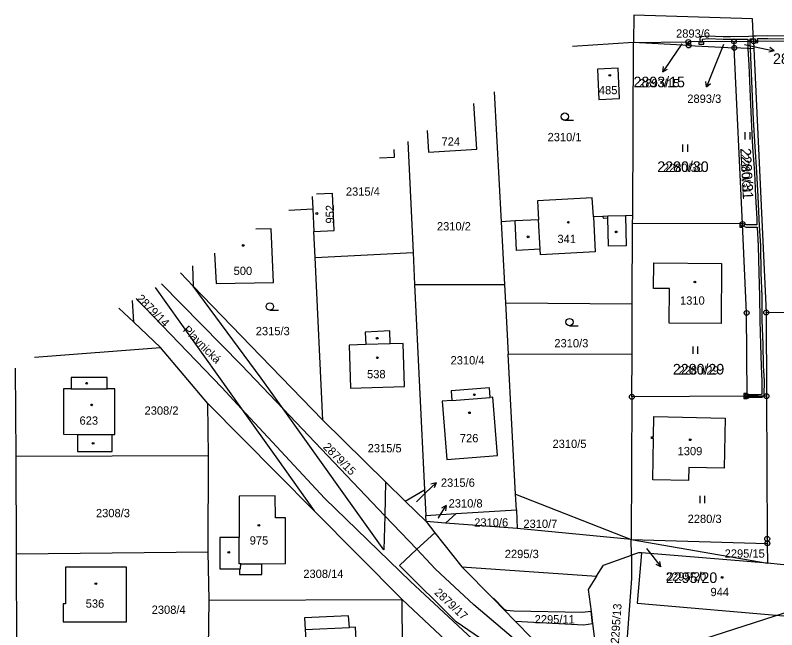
# Model space of a CAD drawing. Extents: x -758836 to -757729, y -1175316 to -1174366.
# Drawn here: x -758589.2 to -758433.4, y -1174763.3 to -1174637.5 of the extents above; entities that cross this region are included whole.
import ezdxf

# ---------------------------------------------------------------- set-up
doc = ezdxf.new("R2010")
doc.units = 0
for name, color, linetype in [('_NOR-pomocná', 7, 'Continuous'), ('Hranice parcel', 7, 'Continuous'), ('Parcelní čísla', 7, 'Continuous'), ('Pop  PČ popisy', 7, 'Continuous'), ('Vnitřní kresba', 7, 'Continuous'), ('Věcná břemena k části', 7, 'Continuous'), ('Značky bodu BP', 7, 'Continuous'), ('Značky budov', 7, 'Continuous'), ('Značky kultur', 7, 'Continuous')]:
    doc.layers.add(name, color=color, linetype=linetype)

msp = doc.modelspace()

# ---------------------------------------------------------------- linework, layer by layer
at = {"layer": '_NOR-pomocná'}
msp.add_lwpolyline([(-758517.54, -1174787.42), (-758417.59, -1174755.22), (-758372.07, -1174896.57), (-758472.01, -1174928.76)], close=True, dxfattribs=at)
at = {"layer": 'Hranice parcel'}
for p, q in [((-758462.68, -1174643.09), (-758475.19, -1174643.89)), ((-758462.85, -1174678.46), (-758462.68, -1174643.09)), ((-758462.68, -1174643.09), (-758451.46, -1174642.95)), ((-758451.39, -1174643.67), (-758462.68, -1174643.09)), ((-758442.12, -1174642.84), (-758451.46, -1174642.95)), ((-758451.46, -1174642.95), (-758451.39, -1174643.67)), ((-758442.12, -1174642.84), (-758438.13, -1174642.79)), ((-758442.06, -1174644.14), (-758442.12, -1174642.84)), ((-758438.13, -1174642.79), (-758413.7, -1174642.5)), ((-758438.13, -1174642.79), (-758438.05, -1174644.35)), ((-758451.39, -1174643.67), (-758442.06, -1174644.14)), ((-758438.05, -1174644.35), (-758442.06, -1174644.14)), ((-758440.39, -1174680.2), (-758442.06, -1174644.14)), ((-758438.05, -1174644.35), (-758435.54, -1174698.32)), ((-758491.19, -1174653.13), (-758489.78, -1174679.76)), ((-758508.89, -1174663.35), (-758507.79, -1174686.07)), ((-758528.42, -1174674.62), (-758528.3, -1174677.14)), ((-758533.22, -1174677.4), (-758528.3, -1174677.14)), ((-758528.3, -1174677.14), (-758528.09, -1174681.75)), ((-758462.86, -1174680.09), (-758462.85, -1174678.46)), ((-758489.78, -1174679.76), (-758489.1, -1174692.62)), ((-758462.93, -1174696.59), (-758462.86, -1174680.09)), ((-758440.39, -1174680.2), (-758462.86, -1174680.09)), ((-758527.85, -1174687.07), (-758528.09, -1174681.75)), ((-758527.85, -1174687.07), (-758507.79, -1174686.07)), ((-758526.24, -1174720.38), (-758527.85, -1174687.07)), ((-758507.79, -1174686.07), (-758507.47, -1174692.57)), ((-758555.41, -1174690.21), (-758552.78, -1174692.96)), ((-758552.91, -1174688.76), (-758552.78, -1174692.96)), ((-758507.47, -1174692.57), (-758489.1, -1174692.62)), ((-758507.47, -1174692.57), (-758505.43, -1174734.65)), ((-758489.1, -1174692.62), (-758488.9, -1174696.33)), ((-758488.9, -1174696.33), (-758488.35, -1174706.88)), ((-758488.9, -1174696.33), (-758462.93, -1174696.59)), ((-758462.98, -1174706.79), (-758462.93, -1174696.59)), ((-758414.62, -1174698.66), (-758435.54, -1174698.32)), ((-758435.54, -1174698.32), (-758435.46, -1174715.46)), ((-758559.48, -1174705.52), (-758564.95, -1174700.34)), ((-758585.29, -1174707.46), (-758559.48, -1174705.52)), ((-758549.77, -1174716.98), (-758559.48, -1174705.52)), ((-758488.35, -1174706.88), (-758462.98, -1174706.79)), ((-758486.83, -1174735.54), (-758488.35, -1174706.88)), ((-758463.02, -1174715.59), (-758462.98, -1174706.79)), ((-758589.2, -1174709.72), (-758589.11, -1174727.75)), ((-758463.02, -1174715.59), (-758463.16, -1174744.79)), ((-758439.46, -1174715.47), (-758463.02, -1174715.59)), ((-758435.46, -1174715.46), (-758439.46, -1174715.47)), ((-758549.68, -1174727.61), (-758549.77, -1174716.98)), ((-758526.24, -1174720.38), (-758513.43, -1174732.97)), ((-758589.11, -1174727.75), (-758549.68, -1174727.61)), ((-758549.7, -1174747.29), (-758549.68, -1174727.61)), ((-758589.11, -1174727.75), (-758589.01, -1174747.74)), ((-758513.43, -1174732.97), (-758509.4, -1174736.93)), ((-758509.4, -1174736.93), (-758505.43, -1174734.65)), ((-758505.43, -1174734.65), (-758505.18, -1174739.86)), ((-758509.4, -1174736.93), (-758505.12, -1174741.14)), ((-758486.66, -1174738.69), (-758486.83, -1174735.54)), ((-758486.83, -1174735.54), (-758463.16, -1174744.79)), ((-758510.04, -1174757.06), (-758528.03, -1174738.91)), ((-758505.18, -1174739.86), (-758498.99, -1174739.47)), ((-758505.12, -1174741.14), (-758505.18, -1174739.86)), ((-758498.99, -1174739.47), (-758501.16, -1174741.44)), ((-758498.99, -1174739.47), (-758486.66, -1174738.69)), ((-758486.66, -1174738.69), (-758486.46, -1174742.55)), ((-758501.16, -1174741.44), (-758505.12, -1174741.14)), ((-758505.12, -1174741.14), (-758503.32, -1174743.41)), ((-758486.46, -1174742.55), (-758501.16, -1174741.44)), ((-758463.16, -1174744.79), (-758486.46, -1174742.55)), ((-758503.32, -1174743.41), (-758497.78, -1174750.4)), ((-758463.16, -1174744.79), (-758435.31, -1174745.59)), ((-758463.12, -1174748.03), (-758463.16, -1174744.79)), ((-758463.16, -1174744.79), (-758435.29, -1174749.65)), ((-758435.31, -1174745.59), (-758435.29, -1174749.65)), ((-758589.01, -1174747.74), (-758549.7, -1174747.29)), ((-758589.01, -1174747.74), (-758588.92, -1174767.73)), ((-758549.49, -1174757.19), (-758549.7, -1174747.29)), ((-758435.29, -1174749.65), (-758461.07, -1174747.52)), ((-758497.78, -1174750.4), (-758470.24, -1174752.31)), ((-758429.95, -1174750.16), (-758435.29, -1174749.65)), ((-758549.63, -1174767.27), (-758549.49, -1174757.19)), ((-758549.49, -1174757.19), (-758510.04, -1174757.06)), ((-758509.88, -1174777.17), (-758510.04, -1174757.06)), ((-758501.06, -1174765.48), (-758510.04, -1174757.06)), ((-758471.37, -1174759.51), (-758471.06, -1174761.99))]:
    msp.add_line(p, q, dxfattribs=at)
for points in [[(-758438.13, -1174642.79), (-758438.34, -1174638.23), (-758462.65, -1174637.48), (-758462.68, -1174643.09)], [(-758469.78, -1174654.76), (-758465.54, -1174654.56), (-758465.83, -1174648.3), (-758470.08, -1174648.5), (-758469.78, -1174654.76)], [(-758504.93, -1174661.06), (-758504.66, -1174665.51), (-758494.75, -1174664.89), (-758495.34, -1174655.52)], [(-758514.67, -1174666.68), (-758511.56, -1174666.52), (-758511.64, -1174664.94)], [(-758528.09, -1174681.75), (-758523.95, -1174681.56), (-758524.31, -1174673.96), (-758527.53, -1174674.11)], [(-758462.85, -1174678.46), (-758464.35, -1174678.51), (-758467.93, -1174678.64), (-758468.93, -1174678.66), (-758470.9, -1174678.72), (-758471.11, -1174674.89), (-758482.35, -1174675.5), (-758482.15, -1174679.34), (-758486.93, -1174679.6), (-758489.78, -1174679.76)], [(-758439.46, -1174715.47), (-758439.54, -1174698.42), (-758440.39, -1174680.2)], [(-758548.41, -1174686.16), (-758548.11, -1174692.38), (-758536.32, -1174692.16), (-758536.83, -1174681.21), (-758539.96, -1174681.29)], [(-758458.58, -1174693.4), (-758458.55, -1174688.18), (-758444.67, -1174688.27), (-758444.76, -1174700.56), (-758455.38, -1174700.51), (-758455.33, -1174693.42), (-758458.58, -1174693.4)], [(-758560.57, -1174693.18), (-758542.88, -1174718.04), (-758535.53, -1174728.37), (-758528.03, -1174738.91)], [(-758552.78, -1174692.96), (-758539.03, -1174707.17), (-758526.24, -1174720.38)], [(-758513.43, -1174732.97), (-758513.55, -1174739.95), (-758513.8, -1174746.93), (-758534.39, -1174718.05), (-758538.89, -1174711.74), (-758552.78, -1174692.96)], [(-758564.95, -1174700.34), (-758565.19, -1174695.86)], [(-758564.95, -1174700.34), (-758567.98, -1174697.47)], [(-758512.53, -1174702.11), (-758517.56, -1174702.34), (-758517.48, -1174704.89), (-758520.88, -1174704.99), (-758520.61, -1174713.81), (-758509.54, -1174713.47), (-758509.81, -1174704.65), (-758512.45, -1174704.73), (-758512.53, -1174702.11)], [(-758579.33, -1174723.26), (-758576.48, -1174723.28), (-758576.48, -1174726.78), (-758569.38, -1174726.78), (-758569.38, -1174723.28), (-758568.82, -1174723.27), (-758568.82, -1174713.94), (-758570.37, -1174713.94), (-758570.37, -1174711.62), (-758577.77, -1174711.65), (-758577.77, -1174713.95), (-758579.33, -1174713.95), (-758579.33, -1174723.26)], [(-758499.86, -1174716.33), (-758501.81, -1174716.48), (-758500.88, -1174728.4), (-758490.54, -1174727.6), (-758491.47, -1174715.66), (-758492.01, -1174715.7), (-758492.16, -1174713.75), (-758500.01, -1174714.36), (-758499.86, -1174716.33)], [(-758435.46, -1174715.46), (-758435.32, -1174744.65), (-758435.31, -1174745.59)], [(-758528.03, -1174738.91), (-758535.61, -1174731.27), (-758549.77, -1174716.98)], [(-758458.53, -1174719.65), (-758443.93, -1174719.93), (-758444.11, -1174730.17), (-758451.37, -1174730.05), (-758451.42, -1174732.69), (-758458.75, -1174732.55), (-758458.61, -1174724.15), (-758458.99, -1174724.14), (-758458.98, -1174723.76), (-758458.6, -1174723.77), (-758458.53, -1174719.65)], [(-758543.34, -1174751.98), (-758538.77, -1174751.93), (-758538.76, -1174749.76), (-758533.87, -1174749.74), (-758533.92, -1174740.33), (-758535.97, -1174740.34), (-758536.01, -1174735.85), (-758543.38, -1174735.9), (-758543.36, -1174744.4), (-758547.35, -1174744.41), (-758547.36, -1174750.79), (-758543.31, -1174750.78), (-758543.34, -1174751.98)], [(-758466.28, -1174780.52), (-758466.54, -1174782.53), (-758466.7, -1174783.79), (-758499, -1174761.63), (-758510.58, -1174750.09), (-758507.04, -1174746.79), (-758503.32, -1174743.41)], [(-758461.07, -1174747.52), (-758461.67, -1174747.53), (-758463.12, -1174748.03)], [(-758461.07, -1174747.52), (-758461.94, -1174757.82), (-758430.38, -1174760.57), (-758429.49, -1174750.29)], [(-758470.24, -1174752.31), (-758468.8, -1174750.02), (-758463.12, -1174748.03)], [(-758463.12, -1174748.03), (-758463.07, -1174752.81), (-758464.86, -1174776.68)], [(-758578.91, -1174757.94), (-758579.4, -1174757.94), (-758579.39, -1174761.63), (-758566.45, -1174761.62), (-758566.46, -1174750.43), (-758578.93, -1174750.46), (-758578.91, -1174757.94)], [(-758497.78, -1174750.4), (-758491.43, -1174756.87), (-758486.91, -1174761.48), (-758479.92, -1174768.61), (-758466.28, -1174780.52)], [(-758470.24, -1174752.31), (-758471.93, -1174755.02), (-758471.37, -1174759.51)], [(-758529.99, -1174760.86), (-758529.84, -1174763.25), (-758529.19, -1174773.23), (-758523.57, -1174772.91), (-758523.49, -1174774.21), (-758519.13, -1174774.01), (-758519.21, -1174772.67), (-758519.57, -1174766.55), (-758519.37, -1174766.54), (-758519.6, -1174762.74), (-758520.82, -1174762.81), (-758521.03, -1174760.42), (-758529.99, -1174760.86)], [(-758471.06, -1174761.99), (-758469.72, -1174772.68), (-758464.86, -1174776.68)]]:
    msp.add_lwpolyline(points, dxfattribs=at)
at = {"layer": 'Pop  PČ popisy'}
for p, q in [((-758452.82, -1174643.33), (-758455.01, -1174646.57)), ((-758444.3, -1174643.49), (-758446.65, -1174649.39)), ((-758439.95, -1174643.49), (-758436.82, -1174644.15)), ((-758436.82, -1174644.15), (-758433.89, -1174644.77)), ((-758433.89, -1174644.77), (-758434.97, -1174645.06)), ((-758433.89, -1174644.77), (-758434.76, -1174644.08)), ((-758455.01, -1174646.57), (-758456.69, -1174649.06)), ((-758456.69, -1174649.06), (-758456.54, -1174647.95)), ((-758456.69, -1174649.06), (-758455.71, -1174648.51)), ((-758446.65, -1174649.39), (-758447.77, -1174652.17)), ((-758447.77, -1174652.17), (-758447.86, -1174651.06)), ((-758447.77, -1174652.17), (-758446.94, -1174651.43)), ((-758505.25, -1174735.25), (-758503.09, -1174733.17)), ((-758503.09, -1174733.17), (-758504.16, -1174733.5)), ((-758503.09, -1174733.17), (-758503.46, -1174734.22)), ((-758507.11, -1174737.06), (-758505.25, -1174735.25)), ((-758502.61, -1174740.36), (-758501.02, -1174737.81)), ((-758501.02, -1174737.81), (-758501.98, -1174738.4)), ((-758501.02, -1174737.81), (-758501.13, -1174738.93)), ((-758502.66, -1174740.44), (-758502.61, -1174740.36)), ((-758460, -1174746.66), (-758458.92, -1174748.03)), ((-758458.92, -1174748.03), (-758457.07, -1174750.4)), ((-758457.07, -1174750.4), (-758457.29, -1174749.3)), ((-758457.07, -1174750.4), (-758458.08, -1174749.91))]:
    msp.add_line(p, q, dxfattribs=at)
at = {"layer": 'Vnitřní kresba'}
for p, q in [((-758470.9, -1174678.72), (-758470.5, -1174685.92)), ((-758468.93, -1174678.66), (-758468.92, -1174679.01)), ((-758468.92, -1174679.01), (-758467.92, -1174678.98)), ((-758467.92, -1174678.98), (-758467.93, -1174678.64)), ((-758467.78, -1174684.77), (-758467.92, -1174678.98)), ((-758464.35, -1174678.51), (-758464.2, -1174684.69)), ((-758486.6, -1174685.67), (-758486.93, -1174679.6)), ((-758481.78, -1174685.4), (-758482.15, -1174679.34)), ((-758481.78, -1174685.4), (-758486.6, -1174685.67)), ((-758481.72, -1174686.55), (-758481.78, -1174685.4)), ((-758464.2, -1174684.69), (-758467.78, -1174684.77)), ((-758470.5, -1174685.92), (-758481.72, -1174686.55)), ((-758559.3, -1174692.46), (-758542.88, -1174709.13)), ((-758546.95, -1174713.65), (-758564.47, -1174695.44)), ((-758512.45, -1174704.73), (-758517.48, -1174704.89)), ((-758542.88, -1174709.13), (-758534.39, -1174718.05)), ((-758577.77, -1174713.95), (-758570.37, -1174713.94)), ((-758542.88, -1174718.04), (-758546.95, -1174713.65)), ((-758499.86, -1174716.33), (-758492.01, -1174715.7)), ((-758525.88, -1174736.38), (-758542.88, -1174718.04)), ((-758534.39, -1174718.05), (-758513.55, -1174739.95)), ((-758576.48, -1174723.28), (-758569.38, -1174723.28)), ((-758508.3, -1174753.37), (-758525.88, -1174736.38)), ((-758513.55, -1174739.95), (-758507.04, -1174746.79)), ((-758543.35, -1174749.79), (-758543.36, -1174744.4)), ((-758507.04, -1174746.79), (-758503.17, -1174750.86)), ((-758543.06, -1174749.77), (-758543.35, -1174749.79)), ((-758543.31, -1174750.78), (-758543.09, -1174750.77)), ((-758543.09, -1174750.77), (-758543.06, -1174749.77)), ((-758543.06, -1174749.77), (-758538.76, -1174749.76)), ((-758495.35, -1174758.17), (-758503.17, -1174750.86)), ((-758490.52, -1174769.94), (-758508.3, -1174753.37)), ((-758472, -1174777.9), (-758495.35, -1174758.17)), ((-758529.84, -1174763.25), (-758520.82, -1174762.81))]:
    msp.add_line(p, q, dxfattribs=at)
at = {"layer": 'Věcná břemena k části'}
msp.add_lwpolyline([(-758430.05, -1174641.8), (-758435.18, -1174641.73), (-758437.57, -1174641.76), (-758438.18, -1174641.8), (-758439.09, -1174641.86), (-758442.87, -1174641.88), (-758444.36, -1174641.9), (-758447.46, -1174641.75), (-758449.02, -1174641.91), (-758449.1, -1174642.48), (-758449.05, -1174642.92), (-758448.55, -1174642.92), (-758448.58, -1174642.37), (-758447.44, -1174642.25), (-758444.36, -1174642.4), (-758442.87, -1174642.38), (-758439.32, -1174642.36), (-758439.31, -1174642.8), (-758438.81, -1174642.8), (-758438.82, -1174642.34), (-758438.15, -1174642.3), (-758437.79, -1174642.28), (-758437.76, -1174642.79), (-758437.26, -1174642.78), (-758437.29, -1174642.26), (-758435.18, -1174642.23), (-758430.05, -1174642.3)], dxfattribs=at)
for points in [[(-758449.29, -1174643.43), (-758448.29, -1174643.41), (-758448.3, -1174642.91), (-758448.55, -1174642.92), (-758449.05, -1174642.92), (-758449.3, -1174642.92)], [(-758438.81, -1174642.8), (-758439.31, -1174642.8), (-758439.3, -1174643.39), (-758439.26, -1174644.29), (-758439.11, -1174647.73), (-758438.9, -1174652.59), (-758438.62, -1174658.85), (-758438.32, -1174664.49), (-758437.93, -1174669.64), (-758437.69, -1174674.61), (-758437.48, -1174679.17), (-758437.42, -1174680.38), (-758439.53, -1174680.36), (-758440.4, -1174680.08), (-758440.37, -1174680.61), (-758439.61, -1174680.86), (-758437.39, -1174680.88), (-758437.15, -1174684.71), (-758437.04, -1174690.21), (-758436.87, -1174695.01), (-758436.83, -1174699.96), (-758436.67, -1174704.86), (-758436.56, -1174709.29), (-758436.41, -1174712.36), (-758436.43, -1174715.04), (-758436.55, -1174715.13), (-758437.17, -1174715.16), (-758438.92, -1174715.19), (-758439.46, -1174715.18), (-758439.46, -1174715.47), (-758436.16, -1174715.46), (-758435.93, -1174715.28), (-758435.91, -1174712.34), (-758436.06, -1174709.27), (-758436.17, -1174704.84), (-758436.33, -1174699.94), (-758436.37, -1174694.99), (-758436.54, -1174690.19), (-758436.65, -1174684.69), (-758436.91, -1174680.62), (-758436.98, -1174679.15), (-758437.19, -1174674.59), (-758437.43, -1174669.6), (-758437.82, -1174664.45), (-758438.12, -1174658.83), (-758438.4, -1174652.57), (-758438.61, -1174647.71), (-758438.76, -1174644.31), (-758438.8, -1174643.37)], [(-758437.26, -1174642.78), (-758437.76, -1174642.79), (-758437.73, -1174643.13), (-758437.23, -1174643.09)], [(-758440.37, -1174680.61), (-758440.39, -1174680.2), (-758440.94, -1174680.2), (-758440.91, -1174680.85), (-758440.36, -1174680.83)], [(-758440.08, -1174715.47), (-758439.46, -1174715.47), (-758439.46, -1174715.18), (-758439.58, -1174715.18), (-758439.58, -1174714.93), (-758440.08, -1174714.93)], [(-758436.16, -1174715.46), (-758439.46, -1174715.47), (-758440.08, -1174715.47), (-758440.08, -1174715.93), (-758439.58, -1174715.93), (-758439.58, -1174715.68), (-758438.92, -1174715.69), (-758437.15, -1174715.66), (-758436.37, -1174715.63)], [(-758473.17, -1174759.76), (-758487.15, -1174759.46), (-758488.65, -1174759.34), (-758489.11, -1174759.1), (-758491.34, -1174756.78), (-758491.43, -1174756.87), (-758486.91, -1174761.48), (-758472.83, -1174762.24), (-758471.06, -1174761.99), (-758471.37, -1174759.51)]]:
    msp.add_lwpolyline(points, close=True, dxfattribs=at)
at = {"layer": 'Značky bodu BP'}
for centre, radius in [((-758451.46, -1174642.95), 0.5), ((-758451.39, -1174643.67), 0.5), ((-758451.46, -1174642.95), 0.0303), ((-758442.12, -1174642.84), 0.5), ((-758442.12, -1174642.84), 0.0303), ((-758438.13, -1174642.79), 0.5), ((-758438.13, -1174642.79), 0.0303), ((-758451.39, -1174643.67), 0.0303), ((-758442.06, -1174644.14), 0.5), ((-758442.06, -1174644.14), 0.0303), ((-758440.39, -1174680.2), 0.5), ((-758440.39, -1174680.2), 0.0303), ((-758439.54, -1174698.42), 0.5), ((-758435.54, -1174698.32), 0.5), ((-758439.54, -1174698.42), 0.0303), ((-758435.54, -1174698.32), 0.0303), ((-758463.02, -1174715.59), 0.5), ((-758439.46, -1174715.47), 0.5), ((-758435.46, -1174715.46), 0.5), ((-758463.02, -1174715.59), 0.0303), ((-758439.46, -1174715.47), 0.0303), ((-758435.46, -1174715.46), 0.0303), ((-758435.32, -1174744.65), 0.5), ((-758435.32, -1174744.65), 0.0303), ((-758435.31, -1174745.59), 0.5), ((-758435.31, -1174745.59), 0.0303)]:
    msp.add_circle(centre, radius, dxfattribs=at)
at = {"layer": 'Značky budov'}
for centre in [(-758467.54, -1174649.78), (-758527.48, -1174678.07), (-758476.02, -1174679.87), (-758466.22, -1174681.84), (-758484.25, -1174682.84), (-758542.55, -1174684.61), (-758450.12, -1174692.09), (-758515.14, -1174703.59), (-758515.11, -1174707.6), (-758574.57, -1174712.81), (-758495.26, -1174715.17), (-758573.55, -1174717.24), (-758496.26, -1174718.85), (-758451.07, -1174724.38), (-758573.26, -1174725.1), (-758539.34, -1174741.89), (-758545.5, -1174747.43), (-758444.55, -1174752.56), (-758572.69, -1174753.83)]:
    msp.add_circle(centre, 0.175, dxfattribs=at)
at = {"layer": 'Značky kultur'}
for p, q in [((-758476.74, -1174658.99), (-758474.99, -1174658.99)), ((-758439.84, -1174662.9), (-758439.84, -1174661.4)), ((-758438.84, -1174662.9), (-758438.84, -1174661.4)), ((-758452.57, -1174665.43), (-758452.57, -1174663.93)), ((-758451.57, -1174665.43), (-758451.57, -1174663.93)), ((-758537.1, -1174697.85), (-758535.35, -1174697.85)), ((-758475.78, -1174701.04), (-758474.03, -1174701.04)), ((-758450.51, -1174706.76), (-758450.51, -1174705.26)), ((-758449.51, -1174706.76), (-758449.51, -1174705.26)), ((-758449.06, -1174737.35), (-758449.06, -1174735.85)), ((-758448.06, -1174737.35), (-758448.06, -1174735.85))]:
    msp.add_line(p, q, dxfattribs=at)
for centre in [(-758476.74, -1174658.24), (-758537.1, -1174697.1), (-758475.78, -1174700.29)]:
    msp.add_circle(centre, 0.75, dxfattribs=at)

# ---------------------------------------------------------------- texts
at = {"layer": 'Parcelní čísla'}
for s, height, p in [('2893/6', 1.7, (-758453.98, -1174642.08)), ('2893/14', 2.175, (-758434.14, -1174647.47)), ('2893/15', 2.175, (-758462.68, -1174652.23)), ('2893/15', 1.7, (-758461.52, -1174652.23)), ('485', 1.7, (-758469.77, -1174653.66)), ('2893/3', 1.7, (-758451.68, -1174655.42)), ('2310/1', 1.7, (-758480.27, -1174663.27)), ('724', 1.7, (-758501.97, -1174664.19)), ('2280/30', 2.175, (-758457.82, -1174669.57)), ('2280/30', 1.7, (-758456.66, -1174669.57)), ('2315/4', 1.7, (-758521.54, -1174674.42)), ('2310/2', 1.7, (-758502.91, -1174681.53)), ('341', 1.7, (-758478.25, -1174684.12)), ('500', 1.7, (-758544.51, -1174690.66)), ('1310', 1.7, (-758453.17, -1174696.73)), ('2315/3', 1.7, (-758539.98, -1174702.98)), ('2310/3', 1.7, (-758478.88, -1174705.47)), ('2310/4', 1.7, (-758500.12, -1174708.96)), ('2280/29', 2.175, (-758454.63, -1174711.03)), ('538', 1.7, (-758517.21, -1174711.79)), ('2280/29', 1.7, (-758453.47, -1174711.03)), ('2308/2', 1.7, (-758562.74, -1174719.25)), ('623', 1.7, (-758576.04, -1174721.3)), ('726', 1.7, (-758498.22, -1174724.9)), ('2310/5', 1.7, (-758479.26, -1174726.06)), ('2315/5', 1.7, (-758517.08, -1174726.96)), ('1309', 1.7, (-758453.66, -1174727.55)), ('2315/6', 1.7, (-758502.1, -1174734.01)), ('2310/8', 1.7, (-758500.52, -1174738.25)), ('2308/3', 1.7, (-758572.68, -1174740.24)), ('2280/3', 1.7, (-758451.61, -1174741.42)), ('2310/6', 1.7, (-758495.28, -1174742.16)), ('2310/7', 1.7, (-758485.22, -1174742.43)), ('975', 1.7, (-758541.22, -1174745.84)), ('2295/3', 1.7, (-758489.02, -1174748.6)), ('2295/15', 1.7, (-758444.04, -1174748.52)), ('2308/14', 1.7, (-758530.25, -1174752.67)), ('2295/20', 1.7, (-758456.06, -1174753.22)), ('2295/20', 2.175, (-758456.06, -1174753.7)), ('944', 1.7, (-758446.93, -1174756.39)), ('536', 1.7, (-758574.78, -1174758.76)), ('2308/4', 1.7, (-758561.28, -1174760.02)), ('2295/11', 1.7, (-758482.91, -1174761.98))]:
    msp.add_text(s, height=height, dxfattribs=at).set_placement(p)
for s, height, rotation, p in [('2280/31', 2.175, 273, (-758440.84, -1174664.74)), ('2280/31', 1.7, 273, (-758440.78, -1174665.89)), ('952', 1.7, 90, (-758523.96, -1174680.12)), ('2879/14', 1.7, 315, (-758564.5, -1174695.63)), ('2879/15', 1.7, 315, (-758526.32, -1174725.99)), ('2879/17', 1.7, 317, (-758503.58, -1174755.82)), ('2295/13', 1.7, 86, (-758465.68, -1174766.17))]:
    msp.add_text(s, height=height, rotation=rotation, dxfattribs=at).set_placement(p)
at = {"layer": 'Pop  PČ popisy'}
msp.add_text('Plavnická', height=1.7, rotation=315, dxfattribs=at).set_placement((-758554.98, -1174702.03))

doc.saveas('drawing.dxf')
